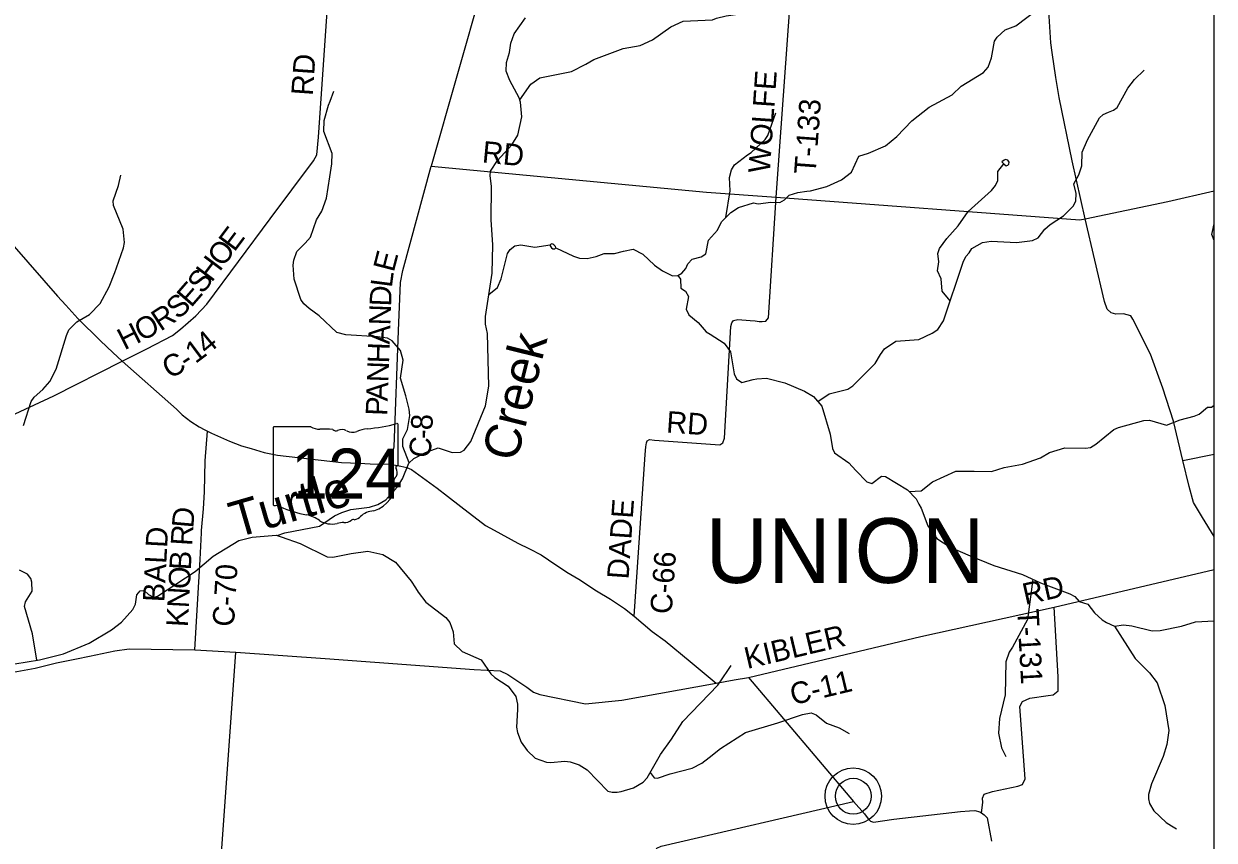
# Model space of a CAD drawing. Extents: x 0 to 1052, y -194 to 246.
# Drawn here: x 5.648 to 8.782, y 15.696 to 17.846 of the extents above; entities that cross this region are included whole.
import ezdxf

# ---------------------------------------------------------------- set-up
doc = ezdxf.new("R2010")
doc.units = 0
for name, color, linetype in [('GM_X_Corporation', 7, 'Continuous'), ('GM_X_County_Road', 7, 'Continuous'), ('GM_X_County_Road_Text', 7, 'Continuous'), ('GM_X_Minor_Lake', 7, 'Continuous'), ('GM_X_Minor_River', 7, 'Continuous'), ('GM_X_Minor_River_Text', 7, 'Continuous'), ('GM_X_State_Location', 7, 'Continuous'), ('GM_X_State_Route', 7, 'Continuous'), ('GM_X_State_Shield', 7, 'Continuous'), ('GM_X_Township_Road', 7, 'Continuous'), ('GM_X_Township_Road_Text', 7, 'Continuous'), ('GM_X_Township_Text', 7, 'Continuous'), ('GM_X_Unincorporated', 7, 'Continuous'), ('GM_X_Unincorporated_Location', 7, 'Continuous')]:
    doc.layers.add(name, color=color, linetype=linetype)

msp = doc.modelspace()

# ---------------------------------------------------------------- linework, layer by layer
at = {"layer": 'GM_X_Corporation'}
for points in [[(2.3779, 14.2055), (8.7822, 14.2055), (8.7822, 20.435)], [(5.491, 17.9457), (5.1788, 17.6981), (4.2749, 17.0262), (3.6964, 16.595), (3.6869, 16.5875), (3.6921, 16.5787), (4.0068, 16.0455), (4.1203, 15.8533), (4.4065, 15.3682), (5.0927, 14.2055), (8.7822, 14.2055), (8.7822, 19.8853)]]:
    msp.add_lwpolyline(points, dxfattribs=at)
at = {"layer": 'GM_X_County_Road'}
msp.add_line((6.0985, 16.1976), (6.1054, 16.3166), dxfattribs=at)
for points in [[(8.4426, 17.3326), (8.4083, 17.4853), (8.3741, 17.6521), (8.3656, 17.7047), (8.3552, 17.7703), (8.3521, 17.7958), (8.3437, 17.9231), (8.3426, 17.9831), (8.3378, 18.088), (8.3374, 18.2452), (8.3338, 18.4518)], [(5.9068, 16.9578), (5.9719, 16.99), (6.0393, 17.0251), (6.0606, 17.0423), (6.101, 17.0769), (6.1295, 17.1081), (6.2963, 17.3321), (6.4108, 17.4855), (6.4192, 17.5012), (6.4234, 17.5474), (6.4665, 18.1706)], [(6.8555, 17.9462), (6.72, 17.4708)], [(6.6128, 16.6866), (6.623, 16.7321), (6.6341, 17.0377), (6.6394, 17.1648), (6.6459, 17.1968), (6.72, 17.4708), (7.4451, 17.4026), (7.6288, 17.3894), (8.4285, 17.3295), (8.4426, 17.3326)], [(8.4426, 17.3326), (8.6605, 17.3785), (8.7822, 17.4058)], [(7.2546, 16.2864), (7.2842, 16.7119), (7.2858, 16.732), (7.2864, 16.7377), (7.2873, 16.743), (7.2889, 16.7482), (7.2954, 16.7515), (7.3087, 16.75), (7.4802, 16.7375), (7.4883, 16.7422), (7.4932, 16.7546), (7.5097, 17.0487), (7.5119, 17.0589), (7.5162, 17.0645), (7.5281, 17.0676), (7.5606, 17.0644), (7.5735, 17.0641), (7.5837, 17.0623), (7.592, 17.0617), (7.6012, 17.063), (7.6082, 17.0715), (7.6288, 17.3894)], [(8.7822, 16.4958), (8.7518, 16.5463), (8.7278, 16.5853), (8.7164, 16.6274), (8.6997, 16.6962), (8.6747, 16.7993), (8.647, 16.8862), (8.6141, 16.9762), (8.568, 17.0681), (8.5625, 17.077), (8.5437, 17.0824), (8.5232, 17.0811), (8.5112, 17.0848), (8.5004, 17.0946), (8.4934, 17.1145), (8.4426, 17.3326)], [(4.2609, 15.8504), (4.2924, 15.8499), (4.4871, 15.8502), (4.5558, 15.8503), (4.5854, 15.8513), (4.7233, 15.8727), (4.7727, 15.8812), (4.8266, 15.8908), (4.86, 15.8975), (4.8741, 15.9005), (4.8794, 15.9077), (4.8841, 15.9278), (4.9141, 16.4089), (4.9327, 16.7033), (5.3736, 16.7026), (5.7266, 16.866), (5.9068, 16.9578)], [(5.9068, 16.9578), (6.0495, 16.8313), (6.0646, 16.816), (6.0873, 16.7984), (6.1092, 16.7849), (6.1247, 16.7764), (6.1311, 16.7732)], [(6.1156, 16.5052), (6.116, 16.5121), (6.1213, 16.5689), (6.1239, 16.6133), (6.125, 16.6948), (6.1311, 16.7732)], [(6.1311, 16.7732), (6.1417, 16.768), (6.1894, 16.7471), (6.2213, 16.7347), (6.2467, 16.7273), (6.2811, 16.7175), (6.316, 16.7105), (6.4841, 16.691), (6.5321, 16.6887)], [(6.5321, 16.6887), (6.5601, 16.6874), (6.6128, 16.6866)], [(6.1054, 16.3166), (6.1124, 16.4356), (6.1156, 16.5052)], [(7.5558, 16.125), (8.0094, 16.2323), (8.3605, 16.3099), (8.7822, 16.4091)], [(5.5514, 16.1267), (5.6776, 16.1495), (5.7337, 16.1636), (5.7864, 16.1736), (5.8211, 16.181), (5.8878, 16.1948), (5.9252, 16.2003), (6.0985, 16.1976), (6.206, 16.1909), (6.4409, 16.1744), (6.8336, 16.1454), (6.9025, 16.1421), (6.9227, 16.1321), (6.9723, 16.0992), (6.9902, 16.0859), (7.0067, 16.0797), (7.1271, 16.0553), (7.2222, 16.0649), (7.471, 16.1097)], [(7.471, 16.1097), (7.5182, 16.1184), (7.5558, 16.125)]]:
    msp.add_lwpolyline(points, dxfattribs=at)
at = {"layer": 'GM_X_Minor_Lake'}
for points in [[(8.2288, 17.4763), (8.234, 17.4721), (8.2386, 17.4735), (8.2413, 17.4761), (8.2425, 17.4818), (8.2385, 17.4872), (8.2328, 17.4884), (8.2294, 17.4873), (8.2228, 17.4825)], [(8.2228, 17.4825), (8.2252, 17.4806), (8.2288, 17.4763)], [(7.0488, 17.2561), (7.0477, 17.2596), (7.0436, 17.2642), (7.0406, 17.2661), (7.0379, 17.2662), (7.0349, 17.2651), (7.0333, 17.2632), (7.0355, 17.2586), (7.0374, 17.2559), (7.0411, 17.2536), (7.0464, 17.2531)], [(7.0464, 17.2531), (7.0488, 17.2561)]]:
    msp.add_lwpolyline(points, dxfattribs=at)
at = {"layer": 'GM_X_Minor_River'}
for points in [[(6.9537, 17.6461), (6.9832, 17.6873), (7.0062, 17.7036), (7.0895, 17.7201), (7.1277, 17.74), (7.1491, 17.7518), (7.2258, 17.7806), (7.2711, 17.7893), (7.3028, 17.804), (7.3515, 17.8382), (7.3843, 17.8528), (7.4609, 17.8569), (7.4716, 17.8606), (7.4968, 17.8674), (7.5404, 17.8728)], [(7.0487, 17.2565), (7.0954, 17.2342), (7.1113, 17.229), (7.1314, 17.2283), (7.155, 17.2332), (7.1759, 17.2416), (7.2029, 17.2408), (7.2265, 17.2469), (7.2523, 17.2522), (7.2779, 17.2393), (7.3089, 17.2104), (7.3292, 17.1956), (7.3555, 17.1823), (7.3703, 17.1832), (7.3806, 17.1895), (7.3907, 17.2015), (7.3962, 17.2139), (7.4074, 17.2263), (7.4314, 17.2327), (7.4436, 17.2405), (7.4506, 17.276), (7.4746, 17.3026), (7.4851, 17.3248), (7.5098, 17.3487), (7.5297, 17.362), (7.569, 17.3747), (7.5814, 17.3722), (7.6145, 17.3766), (7.6384, 17.3759), (7.651, 17.3829), (7.663, 17.3952), (7.6858, 17.4021), (7.7097, 17.4051), (7.7192, 17.4065), (7.7623, 17.4172), (7.8012, 17.4348), (7.8273, 17.4553), (7.8466, 17.4971), (7.8721, 17.5054), (7.9164, 17.5244), (7.9467, 17.549), (7.9857, 17.5905), (8.0314, 17.6266), (8.0922, 17.6594), (8.1156, 17.6814), (8.175, 17.7176), (8.1873, 17.7315), (8.1957, 17.756), (8.1974, 17.7662), (8.2036, 17.8003), (8.211, 17.8108), (8.2321, 17.8302), (8.2596, 17.8403), (8.3145, 17.8816)], [(6.315, 16.4984), (6.3347, 16.5057), (6.4263, 16.5232), (6.4658, 16.5507), (6.4849, 16.5595), (6.5093, 16.5671), (6.5579, 16.5735), (6.5804, 16.5804), (6.6011, 16.5926), (6.6308, 16.6255), (6.6448, 16.648), (6.6618, 16.6887), (6.6748, 16.701), (6.7051, 16.7172), (6.739, 16.7292), (6.7756, 16.7173), (6.7976, 16.7181), (6.8071, 16.7229), (6.8249, 16.7457), (6.8632, 16.8399), (6.872, 16.8918), (6.8689, 17.0306), (6.8636, 17.055), (6.8635, 17.0751), (6.8809, 17.189), (6.8828, 17.2637), (6.8785, 17.3297), (6.8796, 17.4181), (6.8758, 17.4458), (6.8768, 17.4583), (6.8947, 17.4857), (6.9332, 17.5272), (6.9488, 17.5532), (6.9591, 17.6012), (6.9555, 17.6399), (6.9523, 17.651), (6.9276, 17.6965), (6.9181, 17.7217), (6.9192, 17.7444), (6.9268, 17.7704), (6.9303, 17.795), (6.939, 17.8192), (6.9692, 17.8616)], [(7.7386, 16.8514), (7.768, 16.8717), (7.8172, 16.8842), (7.8306, 16.8924), (7.8895, 16.9517), (7.9035, 16.975), (7.914, 16.9897), (7.9439, 17.0104), (8.0046, 17.0144), (8.0398, 17.031), (8.0543, 17.0413), (8.0695, 17.0635), (8.1208, 17.2186), (8.1279, 17.2333), (8.1368, 17.243), (8.1442, 17.2542), (8.1721, 17.2705), (8.1953, 17.2739), (8.2619, 17.2699), (8.3037, 17.2757), (8.3186, 17.2826), (8.3364, 17.3055), (8.3503, 17.3178), (8.3855, 17.3404), (8.4106, 17.3654), (8.4176, 17.379), (8.4187, 17.399), (8.413, 17.4242), (8.4259, 17.4486), (8.4335, 17.4724), (8.4348, 17.5084), (8.4482, 17.5408), (8.4798, 17.5987), (8.4898, 17.6073), (8.504, 17.6135), (8.5173, 17.6186), (8.5269, 17.6253), (8.555, 17.6765), (8.5724, 17.699), (8.5982, 17.7243)], [(6.6627, 16.6896), (6.6458, 16.7326), (6.6457, 16.7527), (6.6579, 16.7775), (6.6641, 16.8142), (6.6629, 16.8309), (6.6539, 16.8663), (6.6399, 16.9132), (6.6471, 16.9605), (6.6395, 16.9853), (6.6176, 17.0114), (6.6055, 17.018), (6.5787, 17.0219), (6.4957, 17.027), (6.4723, 17.033), (6.4256, 17.0774), (6.3994, 17.0964), (6.3855, 17.1087), (6.377, 17.1198), (6.36, 17.1736), (6.3572, 17.2108), (6.3585, 17.2233), (6.3669, 17.2467), (6.3888, 17.2687), (6.4027, 17.2844), (6.4186, 17.3297), (6.4322, 17.353), (6.4449, 17.3873), (6.4538, 17.4433), (6.4592, 17.4774), (6.46, 17.5047), (6.4382, 17.5626), (6.4387, 17.5915), (6.4503, 17.6322), (6.4543, 17.642), (6.4638, 17.6684)], [(7.4967, 17.336), (7.5077, 17.406), (7.5056, 17.4413), (7.5116, 17.4613), (7.5194, 17.4745), (7.5532, 17.5013), (7.5631, 17.5072), (7.6, 17.5415), (7.607, 17.552), (7.6277, 17.6116)], [(8.087, 17.1162), (8.0662, 17.1417), (8.0629, 17.1747), (8.0538, 17.1957), (8.0572, 17.2196), (8.0545, 17.2412), (8.0592, 17.2544), (8.0782, 17.2807), (8.1076, 17.314), (8.1347, 17.3515), (8.1959, 17.4071), (8.2067, 17.4202), (8.2122, 17.4337), (8.2126, 17.4569), (8.228, 17.4773)], [(5.6468, 16.7884), (5.6671, 16.851), (5.6752, 16.8627), (5.6979, 16.8828), (5.7161, 16.9045), (5.7333, 16.9368), (5.7605, 17.0252), (5.7668, 17.0399), (5.7876, 17.0615), (5.8209, 17.0804), (5.849, 17.1099), (5.8728, 17.1531), (5.8878, 17.1912), (5.8922, 17.2037), (5.9101, 17.2561), (5.913, 17.2697), (5.9094, 17.305), (5.8842, 17.3676), (5.8829, 17.3802), (5.8971, 17.4198), (5.9033, 17.4477)], [(8.7822, 17.2752), (8.776, 17.2915), (8.7822, 17.3191)], [(6.8723, 17.1329), (6.8954, 17.1512), (6.9049, 17.1746), (6.9211, 17.2411), (6.9281, 17.252), (6.9404, 17.2616), (6.9564, 17.2636), (6.9934, 17.2578), (7.0338, 17.2638)], [(7.3703, 17.1832), (7.3773, 17.1736), (7.3777, 17.1497), (7.3905, 17.1416), (7.3982, 17.1278), (7.3916, 17.0949), (7.399, 17.08), (7.4233, 17.0591), (7.4449, 17.0349), (7.4547, 17.0287), (7.4915, 17.0054), (7.5089, 16.9823), (7.5186, 16.9241), (7.5241, 16.9112), (7.5387, 16.9015), (7.5681, 16.909), (7.578, 16.9115), (7.6038, 16.9133), (7.6517, 16.9008), (7.7033, 16.8784), (7.7274, 16.8644), (7.749, 16.8394), (7.7709, 16.7651), (7.7775, 16.7274), (7.7827, 16.7164), (7.8201, 16.6896), (7.8388, 16.6696), (7.8679, 16.6399), (7.8811, 16.6359), (7.9064, 16.6545), (7.9167, 16.6543), (7.9745, 16.6189), (7.9976, 16.5947), (8.0046, 16.5809), (8.0105, 16.5706), (8.028, 16.5244), (8.0521, 16.491), (8.0874, 16.4674), (8.1393, 16.4449), (8.2022, 16.4197), (8.2773, 16.3961), (8.3244, 16.3742), (8.4024, 16.3449), (8.4152, 16.3379), (8.4263, 16.3248), (8.4494, 16.3176), (8.4672, 16.2946), (8.487, 16.2768), (8.499, 16.2694), (8.5193, 16.26), (8.5737, 16.175), (8.6122, 16.1368), (8.6322, 16.1104), (8.6518, 16.0509), (8.6629, 15.9851), (8.6577, 15.948), (8.6481, 15.9167), (8.617, 15.8444), (8.609, 15.8168), (8.6088, 15.805), (8.6117, 15.7932), (8.6235, 15.7737), (8.656, 15.7432), (8.6699, 15.7339), (8.6827, 15.7261)], [(7.9789, 16.6143), (8.0108, 16.6161), (8.0404, 16.6399), (8.1015, 16.6682), (8.1501, 16.6678), (8.1955, 16.6675), (8.2295, 16.6779), (8.277, 16.6863), (8.325, 16.703), (8.3487, 16.7167), (8.3891, 16.7297), (8.4437, 16.7281), (8.4566, 16.7305), (8.4708, 16.7391), (8.5177, 16.7778), (8.5299, 16.7829), (8.5973, 16.8016), (8.6117, 16.8021), (8.6566, 16.7893), (8.6925, 16.8035), (8.7298, 16.8132), (8.7424, 16.8183), (8.7647, 16.8365), (8.7749, 16.8364), (8.7822, 16.8414)], [(5.6239, 16.1603), (5.6893, 16.171), (5.7525, 16.1867), (5.8197, 16.2152), (5.8783, 16.25), (5.9047, 16.2701), (5.9345, 16.3033), (5.9415, 16.3176), (5.9457, 16.3419), (5.9538, 16.3527), (5.9648, 16.3533), (5.9764, 16.3429), (5.9896, 16.3359), (5.9995, 16.3384), (6.0987, 16.4039), (6.1468, 16.4442), (6.2141, 16.4856), (6.2488, 16.4941), (6.3122, 16.4992), (6.3258, 16.4952), (6.3755, 16.4778), (6.4467, 16.4421), (6.4611, 16.4419), (6.5094, 16.451), (6.5534, 16.4575), (6.5935, 16.4489), (6.6262, 16.4287), (6.6682, 16.3787), (6.6789, 16.3611), (6.6863, 16.3493), (6.7068, 16.3231), (6.7592, 16.2829), (6.77, 16.2694), (6.778, 16.2447), (6.7809, 16.2131), (6.8022, 16.1935), (6.8523, 16.1711), (6.8775, 16.1343), (6.8879, 16.1242), (6.9236, 16.1021), (6.9436, 16.0744), (6.9479, 16.0546), (6.948, 16.0402), (6.9454, 15.9936), (6.9474, 15.9796), (6.9573, 15.9544), (6.9732, 15.9321), (6.9945, 15.9124), (7.0243, 15.9014), (7.0342, 15.9012), (7.0721, 15.904), (7.0861, 15.9027), (7.1103, 15.8947), (7.1309, 15.8811), (7.1854, 15.8256), (7.1967, 15.8224), (7.21, 15.823), (7.221, 15.8247), (7.253, 15.8337), (7.279, 15.8488), (7.2895, 15.86), (7.3242, 15.9221), (7.3532, 15.9618), (7.3828, 16.0084), (7.4749, 16.1044), (7.5017, 16.1431), (7.5099, 16.1559)], [(5.6823, 16.1699), (5.6703, 16.24), (5.6498, 16.3116), (5.6527, 16.3241), (5.6698, 16.3519), (5.6694, 16.3754), (5.6662, 16.3853), (5.6572, 16.3968), (5.6366, 16.4077)], [(8.3044, 16.3835), (8.2902, 16.2776), (8.2508, 16.2046), (8.2422, 16.1911), (8.2339, 16.1658), (8.2317, 16.0794), (8.2167, 16.017), (8.2138, 15.9776), (8.222, 15.9396), (8.2333, 15.9163)], [(8.5197, 16.2595), (8.5437, 16.2631), (8.5656, 16.2608), (8.6185, 16.2471), (8.6401, 16.2487), (8.6964, 16.26), (8.7326, 16.2708), (8.7822, 16.2734)], [(7.2974, 15.8742), (7.3073, 15.8602), (7.3167, 15.8596), (7.3495, 15.8713), (7.4078, 15.8859), (7.433, 15.8988), (7.4526, 15.9136), (7.4825, 15.9378), (7.548, 15.9797), (7.633, 16.0053), (7.6978, 16.027), (7.721, 16.032), (7.7342, 16.0264), (7.7611, 16.004), (7.7947, 15.9921), (7.8206, 15.9769)]]:
    msp.add_lwpolyline(points, dxfattribs=at)
at = {"layer": 'GM_X_State_Route'}
for points in [[(5.179, 17.6975), (5.4879, 17.3989), (5.5263, 17.3625), (5.5576, 17.3311), (5.6225, 17.26), (5.7363, 17.1292), (5.7582, 17.1047), (5.7902, 17.0703), (5.8502, 17.011), (5.8823, 16.9803), (5.9068, 16.9578)], [(5.9068, 16.9578), (6.0495, 16.8313), (6.0646, 16.816), (6.0873, 16.7984), (6.1092, 16.7849), (6.1247, 16.7764), (6.1311, 16.7732)], [(6.1311, 16.7732), (6.1417, 16.768), (6.1894, 16.7471), (6.2213, 16.7347), (6.2467, 16.7273), (6.2811, 16.7175), (6.316, 16.7105), (6.4841, 16.691), (6.5321, 16.6887)], [(6.5321, 16.6887), (6.5601, 16.6874), (6.6128, 16.6866)], [(6.6128, 16.6866), (6.6409, 16.6807), (6.6565, 16.6775), (6.669, 16.6721), (6.7362, 16.623), (6.7632, 16.6023)], [(6.7632, 16.6023), (6.7986, 16.5751), (6.8178, 16.5601), (6.8439, 16.5394), (6.8639, 16.5248), (6.8862, 16.5125), (6.9487, 16.4782), (6.9797, 16.4635), (7.0104, 16.4474), (7.0296, 16.4347), (7.0773, 16.4024), (7.109, 16.3839), (7.1556, 16.3532), (7.1922, 16.3305), (7.2293, 16.3059), (7.2546, 16.2864), (7.3026, 16.2461), (7.3362, 16.2216), (7.4023, 16.1668), (7.471, 16.1097)], [(7.471, 16.1097), (7.5182, 16.1184), (7.5558, 16.125)], [(7.5558, 16.125), (7.8327, 15.7978), (7.8614, 15.7653), (7.8715, 15.7523), (7.8772, 15.7461), (7.8848, 15.7434), (7.9387, 15.7518), (8.1139, 15.7714), (8.1383, 15.7735), (8.1523, 15.7741), (8.1652, 15.7706), (8.1691, 15.7681), (8.1765, 15.7633), (8.1841, 15.7549), (8.1962, 15.694)]]:
    msp.add_lwpolyline(points, dxfattribs=at)
at = {"layer": 'GM_X_State_Shield'}
for p, q in [((6.3041, 16.7815), (6.3041, 16.5814)), ((6.4039, 16.7849), (6.3074, 16.7849)), ((6.6337, 16.6852), (6.6337, 16.7899)), ((6.6337, 16.6852), (6.6337, 16.6852))]:
    msp.add_line(p, q, dxfattribs=at)
for centre, major_axis, start_param, end_param in [((6.3079, 16.7819), (0.00382, 0), 1.712693, 3.28349), ((6.4269, 16.8082), (0.037, 0), 4.042523, 4.731795), ((6.4392, 16.6726), (0.133, 0), 1.404758, 1.657858), ((6.4694, 16.783), (0.0107, 0), 3.836095, 5.185415), ((6.485, 16.7598), (0.0222, 0), 0.950623, 2.079405), ((6.5137, 16.7915), (0.0267, 0), 4.081561, 5.145723), ((6.5609, 16.7238), (0.0703, 0), 1.699011, 2.107814), ((6.5163, 17.0578), (0.3495, 0), 4.814394, 5.042369), ((6.6301, 16.7903), (0.00367, 0), 6.141152, 7.989035), ((6.6329, 16.6775), (0.00568, 0), 1.883978, 3.671073), ((6.5968, 16.6643), (0.0341, 0), 5.934695, 6.695948), ((6.6298, 16.6848), (0.00393, 0), 5.05454, 6.418171), ((6.6469, 16.6414), (0.0248, 0), 2.387724, 3.262537), ((6.5359, 16.6281), (0.0874, 0), 5.101752, 6.440018), ((6.3079, 16.5809), (0.00385, 0), 3.00124, 4.508301), ((6.3085, 16.6014), (0.0294, 0), 4.665946, 4.897461), ((6.3145, 16.5698), (0.0106, 0), 0.519207, 1.627899), ((6.4484, 16.7496), (0.2524, 0), 4.195997, 4.488961), ((6.3731, 16.4915), (0.079, 0), 0.823519, 1.323587), ((6.5728, 16.5252), (0.0479, 0), 1.647645, 2.488434), ((6.4585, 16.5688), (0.0501, 0), 4.026481, 4.996735), ((6.4875, 16.4996), (0.0412, 0), 1.495662, 1.94098), ((6.4912, 16.5538), (0.0267, 0), 4.691044, 5.507374), ((6.5153, 16.5345), (0.00752, 0), 1.147584, 2.315152), ((6.5121, 16.562), (0.0282, 0), 4.937069, 5.64225)]:
    msp.add_ellipse(centre, major_axis=major_axis, ratio=0.8, start_param=start_param, end_param=end_param, dxfattribs=at)
at = {"layer": 'GM_X_Township_Road'}
msp.add_line((8.6997, 16.6962), (8.7822, 16.7127), dxfattribs=at)
for points in [[(7.6288, 17.3894), (7.6677, 17.9258), (7.6728, 17.9344), (7.7095, 17.9452), (8.3378, 18.088)], [(8.1691, 15.7681), (8.1733, 15.7955), (8.1719, 15.8065), (8.1765, 15.8171), (8.1982, 15.8246), (8.2652, 15.8382), (8.2773, 15.8427), (8.2847, 15.8574), (8.2708, 16.0482), (8.2773, 16.0618), (8.2964, 16.0705), (8.3446, 16.077), (8.3583, 16.0791), (8.3713, 16.0893), (8.3712, 16.1262), (8.3605, 16.3099)], [(6.0855, 14.2055), (6.1602, 15.4723), (6.1603, 15.4735), (6.1641, 15.6003), (6.206, 16.1909)], [(6.7438, 14.2346), (6.6817, 14.5094), (6.665, 14.5677), (6.6668, 14.5919), (6.7, 14.8539), (6.9203, 15.3695), (6.943, 15.5938), (6.9506, 15.5955), (7.3148, 15.5122), (7.3295, 15.5084), (7.3402, 15.5104), (7.3434, 15.5171), (7.3102, 15.6666), (7.3146, 15.6748), (7.3261, 15.6802), (7.8327, 15.7978)]]:
    msp.add_lwpolyline(points, dxfattribs=at)
at = {"layer": 'GM_X_Unincorporated'}
for radius in [0.0744, 0.0472]:
    msp.add_circle((7.8319, 15.812), radius, dxfattribs=at)
at = {"layer": 'GM_X_Unincorporated_Location'}
msp.add_line((7.8319, 15.812), (7.8319, 15.812), dxfattribs=at)

# ---------------------------------------------------------------- texts
at = {"layer": 'GM_X_County_Road_Text'}
for s, height, rotation, p in [('RD', 0.05682, 86.0551, (6.4086, 17.6556)), ('RD', 0.05682, 354.5354, (6.853, 17.4811)), ('E', 0.0568, 53.2694, (6.2022, 17.2434)), ('O', 0.0568, 53.2671, (6.1722, 17.2033)), ('E', 0.0568, 75.5324, (6.6219, 17.1901)), ('H', 0.0568, 53.2671, (6.1423, 17.1632)), ('S', 0.0568, 53.0185, (6.1191, 17.1324)), ('L', 0.0568, 82.5475, (6.6167, 17.1498)), ('E', 0.0568, 48.9574, (6.0884, 17.0969)), ('D', 0.0568, 87.6626, (6.6148, 17.1012)), ('S', 0.0568, 41.1384, (6.0536, 17.0657)), ('R', 0.0568, 33.4369, (6.008, 17.0349)), ('N', 0.0568, 87.9669, (6.613, 17.0513)), ('H', 0.0568, 26.8786, (5.9128, 16.9859)), ('O', 0.0568, 27.2497, (5.9578, 17.0087)), ('A', 0.0568, 87.9669, (6.6112, 17.0013)), ('4', 0.0568, 39.5722, (6.1301, 16.9725)), ('1', 0.0568, 36.7845, (6.0997, 16.9497)), ('H', 0.0568, 87.9669, (6.6095, 16.9513)), ('C', 0.0568, 28.2043, (6.0313, 16.9098)), ('-', 0.0568, 33.4947, (6.0774, 16.9348)), ('N', 0.0568, 87.9669, (6.6077, 16.9014)), ('A', 0.0568, 87.9677, (6.6059, 16.8514)), ('P', 0.0568, 87.9659, (6.6046, 16.8131)), ('8', 0.0568, 87.9014, (6.7236, 16.7753)), ('RD', 0.05682, 356.0551, (7.3382, 16.7698)), ('-', 0.0568, 87.7326, (6.7227, 16.7518)), ('C', 0.0568, 83.79, (6.7174, 16.7011)), ('DADE', 0.05682, 86.0205, (7.2401, 16.3822)), ('D', 0.0568, 84.9995, (6.0939, 16.5166)), ('BALD', 0.05682, 86.9998, (6.0177, 16.3221)), ('R', 0.0568, 86.3952, (6.091, 16.4704)), ('B', 0.0568, 86.9133, (6.0875, 16.4064)), ('C-66', 0.05682, 85.8656, (7.3535, 16.2903)), ('O', 0.0568, 86.9272, (6.0848, 16.3565)), ('C-70', 0.05682, 86.5731, (6.2011, 16.2573)), ('RD', 0.05682, 12.737, (8.2846, 16.3152)), ('N', 0.0568, 86.9258, (6.0822, 16.3066)), ('K', 0.0568, 86.9277, (6.0795, 16.2566)), ('KIBLER', 0.05682, 13.2952, (7.5526, 16.1468)), ('C-11', 0.05682, 13.4563, (7.673, 16.0514))]:
    msp.add_text(s, height=height, rotation=rotation, dxfattribs=at).set_placement(p)
at = {"layer": 'GM_X_Minor_River_Text'}
for s, rotation, p in [('Creek', 75.9834, (6.9454, 16.69)), ('Turtle', 16.1812, (6.2059, 16.4915))]:
    msp.add_text(s, height=0.0947, rotation=rotation, dxfattribs=at).set_placement(p)
at = {"layer": 'GM_X_State_Location'}
msp.add_text('124', height=0.000189, rotation=0, dxfattribs=at).set_placement((6.3984, 16.6543))
for s in ['s', 'r']:
    msp.add_text(s, height=0.000189, dxfattribs=at).set_placement((6.4652, 16.6681))
at = {"layer": 'GM_X_State_Shield'}
msp.add_text('124', height=0.13184, dxfattribs=at).set_placement((6.3507, 16.5955))
at = {"layer": 'GM_X_Township_Road_Text'}
for s, rotation, p in [('WOLFE', 86.0001, (7.6119, 17.4514)), ('T-133', 85.7741, (7.7325, 17.4485)), ('T-131', 273.0864, (8.2632, 16.3037))]:
    msp.add_text(s, height=0.05682, rotation=rotation, dxfattribs=at).set_placement(p)
at = {"layer": 'GM_X_Township_Text'}
msp.add_text('UNION', height=0.17045, rotation=0, dxfattribs=at).set_placement((7.443, 16.3736))

doc.saveas('drawing.dxf')
